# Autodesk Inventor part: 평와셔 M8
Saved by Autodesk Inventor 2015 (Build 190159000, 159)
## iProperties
Created: 2024-12
Part Number: 평와셔 M8
Material: 일반
Document SubType Name: Modeling
Designer: 102-5
Density: 1 g/cm^3
Appearance: 기본값
Author: 102-5
Author: jhkim
Description: 평면 와셔
Creation Date: 2024-11-28
Sending System: Autodesk Inventor 2025
Preprocessor: ST-DEVELOPER v20
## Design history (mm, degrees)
node "평와셔 M81"
body "Solid1"
node "기준1"
